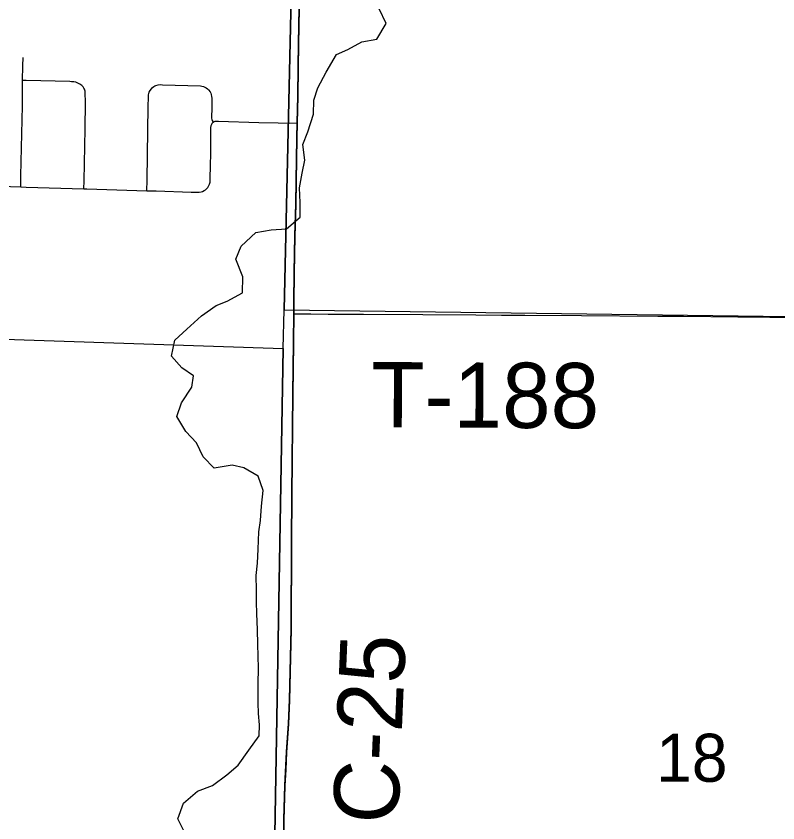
# Model space of a CAD drawing. Extents: x 0 to 34, y 0 to 22.
# Drawn here: x 6.482 to 7.145, y 20.025 to 20.728 of the extents above; entities that cross this region are included whole.
import ezdxf

# ---------------------------------------------------------------- set-up
doc = ezdxf.new("R2010")
doc.units = 0
for name, color, linetype in [('GM_X_County_Road', 7, 'Continuous'), ('GM_X_County_Road_Text', 7, 'Continuous'), ('GM_X_County_Text', 7, 'Continuous'), ('GM_X_Minor_River', 7, 'Continuous'), ('GM_X_Rail_Line_Text', 7, 'Continuous'), ('GM_X_Section', 7, 'Continuous'), ('GM_X_Section_Text', 7, 'Continuous'), ('GM_X_Township_Road', 7, 'Continuous'), ('GM_X_Township_Road_Text', 7, 'Continuous')]:
    doc.layers.add(name, color=color, linetype=linetype)

msp = doc.modelspace()

# ---------------------------------------------------------------- linework, layer by layer
at = {"layer": 'GM_X_County_Road'}
for points in [[(6.72679, 20.63444), (6.72741, 20.65789), (6.72766, 20.68275), (6.72791, 20.70326), (6.72853, 20.73432), (6.72978, 20.79954), (6.7318, 20.9)], [(6.48745, 20.67172), (6.48759, 20.6844), (6.48778, 20.69187)], [(6.48578, 20.57905), (6.48597, 20.58873), (6.4872, 20.64951), (6.48745, 20.67172)], [(6.54086, 20.57737), (6.54098, 20.58438), (6.54178, 20.62963), (6.5421, 20.65248), (6.54203, 20.66123), (6.54195, 20.66228), (6.54169, 20.66331), (6.54132, 20.66425), (6.5408, 20.66515), (6.54008, 20.66617), (6.53911, 20.66727), (6.53737, 20.6685), (6.53545, 20.66944), (6.53363, 20.67011), (6.53198, 20.67047), (6.53006, 20.67062), (6.52859, 20.67071), (6.49054, 20.67164), (6.48745, 20.67172)], [(6.5957, 20.57572), (6.59584, 20.58499), (6.59652, 20.6285), (6.5968, 20.64836), (6.59694, 20.65777), (6.59714, 20.65914), (6.59737, 20.66038), (6.59775, 20.66156), (6.59836, 20.66289), (6.59951, 20.66459), (6.60047, 20.66551), (6.60154, 20.66642), (6.60252, 20.66702), (6.60337, 20.6674), (6.60536, 20.66794), (6.60722, 20.66809), (6.60923, 20.66807), (6.64223, 20.66704), (6.64361, 20.66691), (6.64486, 20.6665), (6.64603, 20.666), (6.64731, 20.66535), (6.64839, 20.66456), (6.64942, 20.66361), (6.65064, 20.66196), (6.6512, 20.6607), (6.65168, 20.65944), (6.65192, 20.65787), (6.65218, 20.65618), (6.65207, 20.64862), (6.65188, 20.63901), (6.65212, 20.63765), (6.65243, 20.63681), (6.65296, 20.63591), (6.65324, 20.63534)], [(6.65324, 20.63534), (6.65433, 20.63604), (6.65501, 20.63619), (6.65635, 20.63632), (6.65788, 20.63625), (6.69324, 20.63523), (6.72679, 20.63444)], [(6.5957, 20.57572), (6.60371, 20.57548), (6.63415, 20.57442), (6.63974, 20.57442), (6.64114, 20.57443), (6.64286, 20.57468), (6.64411, 20.57509), (6.64562, 20.57583), (6.64682, 20.57655), (6.64777, 20.5775), (6.64869, 20.57864), (6.64943, 20.5797), (6.65018, 20.58156), (6.65063, 20.58321), (6.65079, 20.58482), (6.65104, 20.5992), (6.65122, 20.60663), (6.65133, 20.61724), (6.65133, 20.62902), (6.65143, 20.63062), (6.65174, 20.63252), (6.65205, 20.63353), (6.65261, 20.63448), (6.65324, 20.63534)], [(6.72374, 20.46852), (6.7238, 20.47842), (6.72413, 20.5039), (6.72474, 20.53621), (6.72549, 20.56354), (6.7259, 20.58404), (6.72641, 20.6213), (6.72679, 20.63444)], [(6.37295, 20.58254), (6.39244, 20.58186), (6.43091, 20.5807), (6.48578, 20.57905)], [(6.48578, 20.57905), (6.49063, 20.5789), (6.54086, 20.57737)], [(6.54086, 20.57737), (6.54344, 20.57729), (6.5957, 20.57572)], [(6.71681, 20.07137), (6.71755, 20.08645), (6.71914, 20.11125), (6.72016, 20.1317), (6.72147, 20.19383), (6.72184, 20.26965), (6.72195, 20.30942), (6.72226, 20.3411), (6.72257, 20.36843), (6.72287, 20.39826), (6.72357, 20.443), (6.72374, 20.46852)], [(6.71583, 19.96836), (6.71506, 20.00633), (6.71511, 20.02748), (6.71612, 20.05729), (6.71681, 20.07137)]]:
    msp.add_lwpolyline(points, dxfattribs=at)
at = {"layer": 'GM_X_County_Text'}
for points in [[(6.71482, 20.00688), (6.71487, 20.02803), (6.71588, 20.05785), (6.71731, 20.08701), (6.71891, 20.1118), (6.71992, 20.13226), (6.72123, 20.19438), (6.7216, 20.2702), (6.72171, 20.30997), (6.72203, 20.34165), (6.72233, 20.36898), (6.72264, 20.39881), (6.72333, 20.44356), (6.7235, 20.46908), (6.72356, 20.47897), (6.7239, 20.50446), (6.7245, 20.53676), (6.72526, 20.5641), (6.72567, 20.5846), (6.72617, 20.62185), (6.72655, 20.63499), (6.72717, 20.65845), (6.72742, 20.6833), (6.72767, 20.70382), (6.7283, 20.73487)], [(6.7283, 20.73487), (6.72767, 20.70382), (6.72742, 20.6833), (6.72717, 20.65845), (6.72655, 20.63499), (6.72617, 20.62185), (6.72567, 20.5846), (6.72526, 20.5641), (6.7245, 20.53676), (6.7239, 20.50446), (6.72356, 20.47897), (6.7235, 20.46908), (6.72333, 20.44356), (6.72264, 20.39881), (6.72233, 20.36898), (6.72203, 20.34165), (6.72171, 20.30997), (6.7216, 20.2702), (6.72123, 20.19438), (6.71992, 20.13226), (6.71891, 20.1118), (6.71731, 20.08701), (6.71588, 20.05785), (6.71487, 20.02803), (6.71482, 20.00688)]]:
    msp.add_lwpolyline(points, dxfattribs=at)
at = {"layer": 'GM_X_Minor_River'}
msp.add_lwpolyline([(6.62998, 20.01411), (6.62268, 20.02867), (6.62749, 20.04224), (6.63982, 20.05263), (6.65281, 20.05769), (6.66513, 20.06693), (6.67515, 20.07547), (6.6845, 20.08857), (6.69346, 20.10092), (6.69365, 20.11041), (6.6927, 20.12029), (6.69251, 20.12978), (6.69244, 20.14611), (6.6927, 20.15977), (6.69253, 20.17039), (6.69235, 20.18064), (6.69183, 20.19318), (6.69135, 20.20761), (6.69116, 20.21748), (6.69098, 20.22773), (6.69085, 20.24064), (6.69182, 20.25125), (6.69243, 20.26338), (6.6931, 20.27855), (6.69443, 20.28839), (6.69543, 20.3009), (6.69683, 20.31454), (6.69252, 20.32714), (6.68014, 20.33422), (6.66995, 20.33669), (6.65435, 20.33396), (6.64469, 20.34402), (6.63886, 20.35627), (6.62956, 20.36595), (6.62185, 20.379), (6.62588, 20.39106), (6.63486, 20.40455), (6.63619, 20.4144), (6.62608, 20.42142), (6.61718, 20.43147), (6.6201, 20.44545), (6.63052, 20.45512), (6.64326, 20.46663), (6.65595, 20.47588), (6.6655, 20.47949), (6.67892, 20.48681), (6.67919, 20.50085), (6.67304, 20.51615), (6.6778, 20.52745), (6.69055, 20.53934), (6.70387, 20.54174), (6.71715, 20.54262), (6.72911, 20.55264), (6.72897, 20.56554), (6.72846, 20.57808), (6.73098, 20.59093), (6.7331, 20.60228), (6.73146, 20.61597), (6.73585, 20.6269), (6.74069, 20.64236), (6.74093, 20.6545), (6.74455, 20.66544), (6.75164, 20.67896), (6.76066, 20.69435), (6.7706, 20.69871), (6.78287, 20.7053), (6.7958, 20.7077), (6.80403, 20.72121), (6.79783, 20.73423)], dxfattribs=at)
at = {"layer": 'GM_X_Rail_Line_Text'}
for points in [[(6.72463, 20.9), (5.72808, 20.9), (5.71695, 20.4716), (6.7143, 20.43816), (6.71507, 20.47188)], [(7.67137, 20.9), (6.72463, 20.9), (6.71507, 20.47188), (7.65944, 20.45935)]]:
    msp.add_lwpolyline(points, close=True, dxfattribs=at)
at = {"layer": 'GM_X_Section'}
for points in [[(5.71695, 20.4716), (6.7143, 20.43816), (6.69788, 19.47262), (6.6975, 19.43966), (5.68333, 19.46665)], [(6.71507, 20.47188), (7.65944, 20.45935), (7.63985, 19.45485), (6.69788, 19.47262), (6.7143, 20.43816)]]:
    msp.add_lwpolyline(points, close=True, dxfattribs=at)
at = {"layer": 'GM_X_Township_Road'}
msp.add_lwpolyline([(6.72374, 20.46852), (6.72806, 20.46848), (6.73847, 20.46839), (6.75345, 20.46812), (6.7701, 20.46809), (6.78439, 20.46809), (6.83598, 20.46784), (6.88197, 20.46756), (6.90435, 20.46739), (6.92485, 20.46735), (6.97396, 20.46693), (7.04047, 20.46638), (7.06285, 20.46635), (7.11009, 20.46592), (7.13805, 20.46563), (7.17473, 20.46564), (7.20829, 20.46536), (7.22001, 20.4651)], dxfattribs=at)

# ---------------------------------------------------------------- texts
at = {"layer": 'GM_X_County_Road_Text'}
msp.add_text('C-25', height=0.056818, rotation=87.62856, dxfattribs=at).set_placement((6.81429, 20.02355))
at = {"layer": 'GM_X_Section_Text'}
msp.add_text('18', height=0.041856, rotation=0.00001, dxfattribs=at).set_placement((7.03899, 20.06091))
at = {"layer": 'GM_X_Township_Road_Text'}
msp.add_text('T-188', height=0.056818, rotation=359.71909, dxfattribs=at).set_placement((6.79089, 20.36974))

doc.saveas('drawing.dxf')
